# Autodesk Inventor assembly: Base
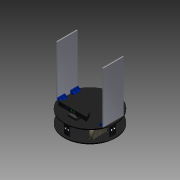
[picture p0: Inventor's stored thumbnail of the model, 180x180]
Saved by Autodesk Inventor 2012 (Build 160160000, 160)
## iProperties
Created: 2014-02
Part Number: Base
Document SubType Name: Assembly
Designer: Aser
Author: Aser
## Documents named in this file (11)
- D:\TechDev\Robotics\ROSADP\MockUp\MobileBase\Base.iam
- D:\TechDev\Robotics\ROSADP\MockUp\MobileBase\Mobile_Baes_Base.ipt
- D:\TechDev\Robotics\ROSADP\MockUp\MobileBase\SG775125000-40K.ipt
- D:\TechDev\Robotics\ROSADP\MockUp\MobileBase\Wheel.ipt
- D:\TechDev\Robotics\ROSADP\MockUp\MobileBase\Sealed Lead Acid Battery 12V - 12Ah.ipt
- D:\TechDev\Robotics\ROSADP\MockUp\MobileBase\Mobile_Baes_Top.ipt
- D:\TechDev\Robotics\ROSADP\Imported Components\UltraSonicSensor\UltraSonicSensor.iam
- D:\TechDev\Robotics\ROSADP\MockUp\MobileBase\Struts.ipt
- D:\TechDev\Robotics\ROSADP\Imported Components\kinect-sensor\kinect sensor.ipt
- D:\TechDev\Robotics\ROSADP\MockUp\MobileBase\Gusseted Angle Bracket.ipt
- D:\TechDev\Robotics\ROSADP\MockUp\Torso\OutterSides.ipt
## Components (22 placed, 10 different names)
1. Mobile_Baes_Base:1 — Angle:1, Mate:3, Flush:2, Flush:3, Mate:4, Mate:7, Mate:8, Mate:9, Mate:12, Mate:13, Mate:14, Mate:17, Mate:18, Mate:19, Mate:22, Mate:23, Mate:24, Mate:25, Mate:26, Mate:27
2. SG775125000-40K:1 — Mate:1, Mate:2, Flush:1, Angle:1, Mate:3, Flush:3, Mate:4, Flush:4
3. SG775125000-40K:2 — Mate:1, Mate:2, Flush:1, Flush:2, Mate:6, Flush:5, Mate:10, Mate:11
4. Wheel:1 — Mate:5, Flush:4
5. Wheel:2 — Mate:5, Mate:6, Flush:5
6. Sealed Lead Acid Battery 12V - 12Ah:1 — Mate:7, Angle:2, Mate:10, Mate:11
7. Mobile_Baes_Top:1 — Mate:8, Mate:9, Mate:32, Mate:33, Mate:34, Mate:35, Mate:36, Mate:37, Tangent:1, Tangent:2, Tangent:3, Tangent:4
8. UltraSonicSensor:1 [sub-assembly] — Angle:2, Flush:6, Flush:7, Flush:9, Flush:10, Mate:15, Mate:16, Mate:28
9. UltraSonicSensor:2 [sub-assembly] — Flush:6, Flush:8, Mate:31
10. UltraSonicSensor:3 [sub-assembly] — Flush:7, Flush:8, Mate:20, Mate:21, Mate:29
11. UltraSonicSensor:4 [sub-assembly] — Flush:9, Flush:10, Mate:30
12. Struts:1 — Mate:12, Mate:13, Mate:14, Mate:15, Mate:16, Mate:28
13. Struts:2 — Mate:17, Mate:18, Mate:19, Mate:20, Mate:21, Mate:29
14. Struts:3 — Mate:22, Mate:23, Mate:24, Mate:30, Flush:11, Flush:12, Angle:3
15. Struts:4 — Mate:25, Mate:26, Mate:27, Mate:31
16. kinect sensor:1 — Mate:32, Flush:11, Flush:12
17. Gusseted Angle Bracket:1 — Mate:34, Flush:13, Flush:16, Mate:39
18. Gusseted Angle Bracket:2 — Mate:33, Flush:14, Flush:15, Flush:17
19. Gusseted Angle Bracket:3 — Mate:35, Flush:13, Flush:14
20. Gusseted Angle Bracket:4 — Mate:36, Flush:15, Flush:16, Mate:38, Flush:18
21. OutterSides:1 — Mate:37, Tangent:1, Tangent:2, Angle:3, Mate:38, Flush:17, Flush:18, Flush:19, Flush:20
22. OutterSides:2 — Flush:19, Flush:20, Tangent:3, Tangent:4, Mate:39
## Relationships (66: Mate 39, Flush 20, Tangent 4, Angle 3)
- Mate:1: SG775125000-40K:1 ↔ SG775125000-40K:2
- Mate:2: SG775125000-40K:1 ↔ SG775125000-40K:2
- Flush:1: SG775125000-40K:1 ↔ SG775125000-40K:2
- Angle:1: Mobile_Baes_Base:1 ↔ SG775125000-40K:1
- Mate:3: Mobile_Baes_Base:1 ↔ SG775125000-40K:1
- Flush:2: Mobile_Baes_Base:1 ↔ SG775125000-40K:2
- Flush:3: Mobile_Baes_Base:1 ↔ SG775125000-40K:1
- Mate:4: Mobile_Baes_Base:1 ↔ SG775125000-40K:1
- Mate:5: Wheel:1 ↔ Wheel:2
- Mate:6: SG775125000-40K:2 ↔ Wheel:2
- Flush:4: SG775125000-40K:1 ↔ Wheel:1
- Flush:5: SG775125000-40K:2 ↔ Wheel:2
- Mate:7: Mobile_Baes_Base:1 ↔ Sealed Lead Acid Battery 12V - 12Ah:1
- Mate:8: Mobile_Baes_Base:1 ↔ Mobile_Baes_Top:1
- Mate:9: Mobile_Baes_Base:1 ↔ Mobile_Baes_Top:1
- Angle:2: Sealed Lead Acid Battery 12V - 12Ah:1 ↔ UltraSonicSensor:1
- Mate:10: SG775125000-40K:2 ↔ Sealed Lead Acid Battery 12V - 12Ah:1
- Mate:11: SG775125000-40K:2 ↔ Sealed Lead Acid Battery 12V - 12Ah:1
- Flush:6: UltraSonicSensor:1 ↔ UltraSonicSensor:2
- Flush:7: UltraSonicSensor:1 ↔ UltraSonicSensor:3
- Flush:8: UltraSonicSensor:2 ↔ UltraSonicSensor:3
- Flush:9: UltraSonicSensor:1 ↔ UltraSonicSensor:4
- Flush:10: UltraSonicSensor:1 ↔ UltraSonicSensor:4
- Mate:12: Mobile_Baes_Base:1 ↔ Struts:1
- Mate:13: Mobile_Baes_Base:1 ↔ Struts:1
- Mate:14: Mobile_Baes_Base:1 ↔ Struts:1
- Mate:15: UltraSonicSensor:1 ↔ Struts:1
- Mate:16: UltraSonicSensor:1 ↔ Struts:1
- Mate:17: Mobile_Baes_Base:1 ↔ Struts:2
- Mate:18: Mobile_Baes_Base:1 ↔ Struts:2
- Mate:19: Mobile_Baes_Base:1 ↔ Struts:2
- Mate:20: UltraSonicSensor:3 ↔ Struts:2
- Mate:21: UltraSonicSensor:3 ↔ Struts:2
- Mate:22: Mobile_Baes_Base:1 ↔ Struts:3
- Mate:23: Mobile_Baes_Base:1 ↔ Struts:3
- Mate:24: Mobile_Baes_Base:1 ↔ Struts:3
- Mate:25: Mobile_Baes_Base:1 ↔ Struts:4
- Mate:26: Mobile_Baes_Base:1 ↔ Struts:4
- Mate:27: Mobile_Baes_Base:1 ↔ Struts:4
- Mate:28: UltraSonicSensor:1 ↔ Struts:1
- Mate:29: UltraSonicSensor:3 ↔ Struts:2
- Mate:30: UltraSonicSensor:4 ↔ Struts:3
- Mate:31: UltraSonicSensor:2 ↔ Struts:4
- Mate:32: Mobile_Baes_Top:1 ↔ kinect sensor:1
- Flush:11: Struts:3 ↔ kinect sensor:1
- Flush:12: Struts:3 ↔ kinect sensor:1
- Mate:33: Mobile_Baes_Top:1 ↔ Gusseted Angle Bracket:2
- Mate:34: Mobile_Baes_Top:1 ↔ Gusseted Angle Bracket:1
- Mate:35: Mobile_Baes_Top:1 ↔ Gusseted Angle Bracket:3
- Mate:36: Mobile_Baes_Top:1 ↔ Gusseted Angle Bracket:4
- Flush:13: Gusseted Angle Bracket:1 ↔ Gusseted Angle Bracket:3
- Flush:14: Gusseted Angle Bracket:2 ↔ Gusseted Angle Bracket:3
- Flush:15: Gusseted Angle Bracket:2 ↔ Gusseted Angle Bracket:4
- Flush:16: Gusseted Angle Bracket:1 ↔ Gusseted Angle Bracket:4
- Mate:37: Mobile_Baes_Top:1 ↔ OutterSides:1
- Tangent:1: Mobile_Baes_Top:1 ↔ OutterSides:1
- Tangent:2: Mobile_Baes_Top:1 ↔ OutterSides:1
- Angle:3: Struts:3 ↔ OutterSides:1
- Mate:38: Gusseted Angle Bracket:4 ↔ OutterSides:1
- Flush:17: Gusseted Angle Bracket:2 ↔ OutterSides:1
- Flush:18: Gusseted Angle Bracket:4 ↔ OutterSides:1
- Flush:19: OutterSides:1 ↔ OutterSides:2
- Flush:20: OutterSides:1 ↔ OutterSides:2
- Tangent:3: Mobile_Baes_Top:1 ↔ OutterSides:2
- Tangent:4: Mobile_Baes_Top:1 ↔ OutterSides:2
- Mate:39: Gusseted Angle Bracket:1 ↔ OutterSides:2
